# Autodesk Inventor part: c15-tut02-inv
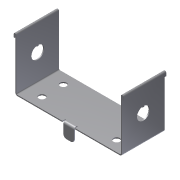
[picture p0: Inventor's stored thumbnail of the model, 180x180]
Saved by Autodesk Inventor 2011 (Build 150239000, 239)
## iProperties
Created: 2010-05
Part Number: c15-tut02-inv
Material: Default
Document SubType Name: Sheet Metal
Designer: CADSoft
Density: 1 g/cm^3
Sheet Metal Rule: Default_mm
Flat Pattern Width: 5.12619 cm
Flat Pattern Length: 20.3859 cm
Flat Pattern Area: 104.502 cm^2
Sheet Metal Width: 51.262 mm
Sheet Metal Length: 203.859 mm
Sheet Metal Area: 10450.224 mm^2
Author: CADSoft
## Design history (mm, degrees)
node "Face1"
  sketch "Sketch1"
    geometry: L1 (0, 0)-(100, 0); L2 (100, 0)-(100, 40); L3 (100, 40)-(0, 40); L4 (0, 40)-(0, 0)
    constraints: 8 end point, 2 parallel, 1 horizontal, 1 perpendicular
    dimensions: "d0" = 100 distance of L2.end L3.end; "d1" = 40 distance of L1.end L2.end
hole "Hole1" diameter "d5" = 6; stored, may be unused: countersink angle "d9" = 90 deg, drill point angle "d11" = 118 deg; dims "d3" = 15, "d4" = 10, "d6" = 6, "d7" = 4, "d8" = 2, "d10" = 1 (= Thickness)
pattern_linear "Rectangular Pattern1" dims "d14" = 70
node "Flange1"
node "Flange2"
feature "Hem1" dims "d38" = 1 (= BendReliefWidth), "d39" = 0.5 (= BendReliefDepth), "d40" = 2 (= MinimumRemnant), "d41" = 1 (= BendRadius), "d42" = 4 (= 4 x Thickness), "d43" = 0.5 (= 0.5 x Thickness), "d44" = 0.25 (= 0.5 x d43), "SeamGap" = 0.01, "Thickness" = 1 (derived)
feature "Hem2" dims "d45" = 1 (= BendReliefWidth), "d46" = 0.5 (= BendReliefDepth), "d47" = 2 (= MinimumRemnant), "d48" = 1 (= BendRadius), "d49" = 4 (= 4 x Thickness), "d50" = 0.5 (= 0.5 x Thickness), "d51" = 0.25 (= 0.5 x d50), "SeamGap" = 0.01, "Thickness" = 1 (derived)
sketch "Sketch6"
  geometry: L1 (0, 40)-(0, 0) reference; L2 (48, 0)-(0, 0) reference; 2 further points
  dimensions: "d52" = 25 distance from line of L1 point (25, 20); "d54" = 20 distance from line of point (25, 20) L2
feature "iFeature15:1" sketch "Sketch6"
sketch "Sketch8"
  geometry: 2 further points
feature "iFeature15:2" sketch "Sketch8"
node "Flange3"
feature "Corner Round1" dims "d78" = 3
body "Solid1"
face "Plate1" dims "Thickness" = 1 (derived)
sketch "Sketch2"
  geometry: L1 (0, -50)-(40, -50); L2 (40, -50)-(40, 0); 2 other entities
  constraints: 4 end point, 4 other
face "Plate2" dims "d18" = 1 (= BendReliefWidth), "d19" = 0.5 (= BendReliefDepth), "d20" = 2 (= MinimumRemnant), "d21" = 1 (= BendRadius), "d22" = 50, "d23" = 90 deg, "d24" = 1 (= BendRadius), "d25" = 4 (= CornerReliefSize), "d26" = 1 (= GapSize), "d27" = 1 (= JacobiRadiusSize), "SeamGap" = 0.01, "Thickness" = 1 (derived)
bend "Bend1" dims "d18" = 1 (= BendReliefWidth), "d19" = 0.5 (= BendReliefDepth), "d20" = 2 (= MinimumRemnant), "d21" = 1 (= BendRadius), "d22" = 50, "d23" = 90 deg, "d24" = 1 (= BendRadius), "SeamGap" = 0.01, "Thickness" = 1 (derived)
feature "Corner1" dims "d22" = 50, "d23" = 90 deg, "d25" = 4 (= CornerReliefSize), "d26" = 1 (= GapSize), "d27" = 1 (= JacobiRadiusSize)
sketch "Sketch3"
  geometry: L1 (0, -50)-(40, -50); L2 (40, -50)-(40, 0); 2 other entities
  constraints: 4 end point, 4 other
face "Plate3" dims "d28" = 1 (= BendReliefWidth), "d29" = 0.5 (= BendReliefDepth), "d30" = 2 (= MinimumRemnant), "d31" = 1 (= BendRadius), "d32" = 50, "d33" = 90 deg, "d34" = 1 (= BendRadius), "d35" = 4 (= CornerReliefSize), "d36" = 1 (= GapSize), "d37" = 1 (= JacobiRadiusSize), "SeamGap" = 0.01, "Thickness" = 1 (derived)
bend "Bend2" dims "d28" = 1 (= BendReliefWidth), "d29" = 0.5 (= BendReliefDepth), "d30" = 2 (= MinimumRemnant), "d31" = 1 (= BendRadius), "d32" = 50, "d33" = 90 deg, "d34" = 1 (= BendRadius), "SeamGap" = 0.01, "Thickness" = 1 (derived)
feature "Corner2" dims "d32" = 50, "d33" = 90 deg, "d35" = 4 (= CornerReliefSize), "d36" = 1 (= GapSize), "d37" = 1 (= JacobiRadiusSize)
sketch "Sketch9"
  geometry: L1 (-53, 0)-(-43, 0); L2 (-43, 0)-(-43, 13); L3 (-43, 13)-(-53, 13); L4 (-53, 13)-(-53, 0)
  constraints: 8 end point
face "Plate4" dims "d67" = 1 (= BendReliefWidth), "d68" = 0.5 (= BendReliefDepth), "d69" = 2 (= MinimumRemnant), "d70" = 1 (= BendRadius), "d71" = 10, "d72" = 13, "d73" = 90 deg, "d74" = 1 (= BendRadius), "d75" = 4 (= CornerReliefSize), "d76" = 1 (= GapSize), "d77" = 1 (= JacobiRadiusSize), "SeamGap" = 0.01, "Thickness" = 1 (derived)
bend "Bend3" dims "d67" = 1 (= BendReliefWidth), "d68" = 0.5 (= BendReliefDepth), "d69" = 2 (= MinimumRemnant), "d70" = 1 (= BendRadius), "d72" = 13, "d73" = 90 deg, "d74" = 1 (= BendRadius), "SeamGap" = 0.01, "Thickness" = 1 (derived)
feature "Corner3" dims "d72" = 13, "d73" = 90 deg, "d75" = 4 (= CornerReliefSize), "d76" = 1 (= GapSize), "d77" = 1 (= JacobiRadiusSize)
sketch "Sketch4"
  geometry: L1 (1, 0)-(0, 0); L2 (-0.5, 0)-(-0.5, -2.75); L3 (-0.5, -2.75)-(-1.5, -2.75); L4 (-1.5, -2.75)-(-1.5, 0); A1 r 0.25 centre (-0.25, 0) between (0, 0) and (-0.5, 0); A2 r 1.25 centre (-0.25, 0) between (1, 0) and (-1.5, 0)
  constraints: 8 end point, 4 point on circle
sketch "Sketch5"
  geometry: L1 (1, 0)-(0, 0); L2 (-0.5, 0)-(-0.5, -2.75); L3 (-0.5, -2.75)-(-1.5, -2.75); L4 (-1.5, -2.75)-(-1.5, 0); A1 r 0.25 centre (-0.25, 0) between (0, 0) and (-0.5, 0); A2 r 1.25 centre (-0.25, 0) between (1, 0) and (-1.5, 0)
  constraints: 8 end point, 4 point on circle
feature "Definition1"
other parameters: "BendRadius" = 1 (= Thickness), "BendReliefWidth" = 1 (= Thickness), "BendReliefDepth" = 0.5 (= 0.5 x Thickness), "CornerReliefSize" = 4 (= 4 x Thickness), "MinimumRemnant" = 2 (= 2 x Thickness), "TransitionRadius" = 1 (= BendRadius), "JacobiRadiusSize" = 1 (= BendRadius), "GapSize" = 1 (= Thickness), "d2" = 1 (= BendRadius), "d60" = 90 deg, "d66" = 270 deg, "BendRadius" = 1, "BendReliefDepth" = 0.5, "BendReliefWidth" = 1, "CornerReliefSize" = 4, "GapSize" = 1, "JacobiRadiusSize" = 1, "MinimumRemnant" = 2, "Thickness" = 1, "TransitionRadius" = 1
